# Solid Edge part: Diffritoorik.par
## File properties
Author: Türk
Template: Iso Part.par
Last saved by: Türk
Revision: 8
Application: Solid Edge
Accuracy: 0,990
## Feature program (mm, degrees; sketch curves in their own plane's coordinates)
pattern "PatternOccurrence_1"  XOffset = 32.7273 deg
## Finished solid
Body 1: solid body, 91 faces, 243 edges, 154 vertices.
  Faces by surface: spline 55, plane 24, cone 11, cylinder 1
  Edges by curve: curve on surface 110, line 66, circle 45, spline 22
Bounding box of the edges (mm; curved faces can reach further): 59.861 x 112.500 x 59.336, from (-29.9308, -12.5, -30) to (29.9308, 100, 29.3362).
Cylindrical faces by radius (mm): R27.5 x1
Conical faces (half-angle, radius in mm at the cone's reference point): 45 deg R30 x11
Planar faces by outward normal: +y 12, -y 12
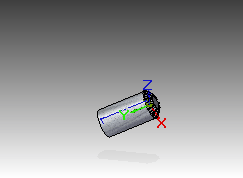
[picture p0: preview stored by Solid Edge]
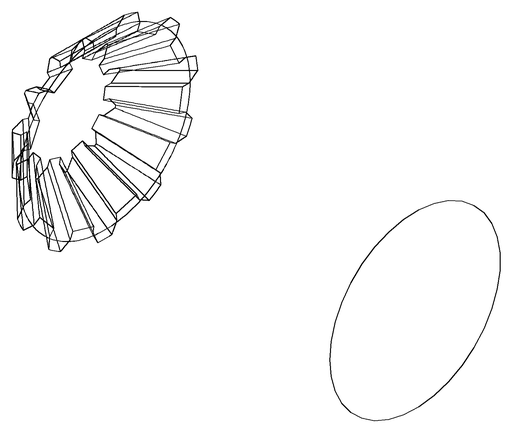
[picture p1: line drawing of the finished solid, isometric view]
